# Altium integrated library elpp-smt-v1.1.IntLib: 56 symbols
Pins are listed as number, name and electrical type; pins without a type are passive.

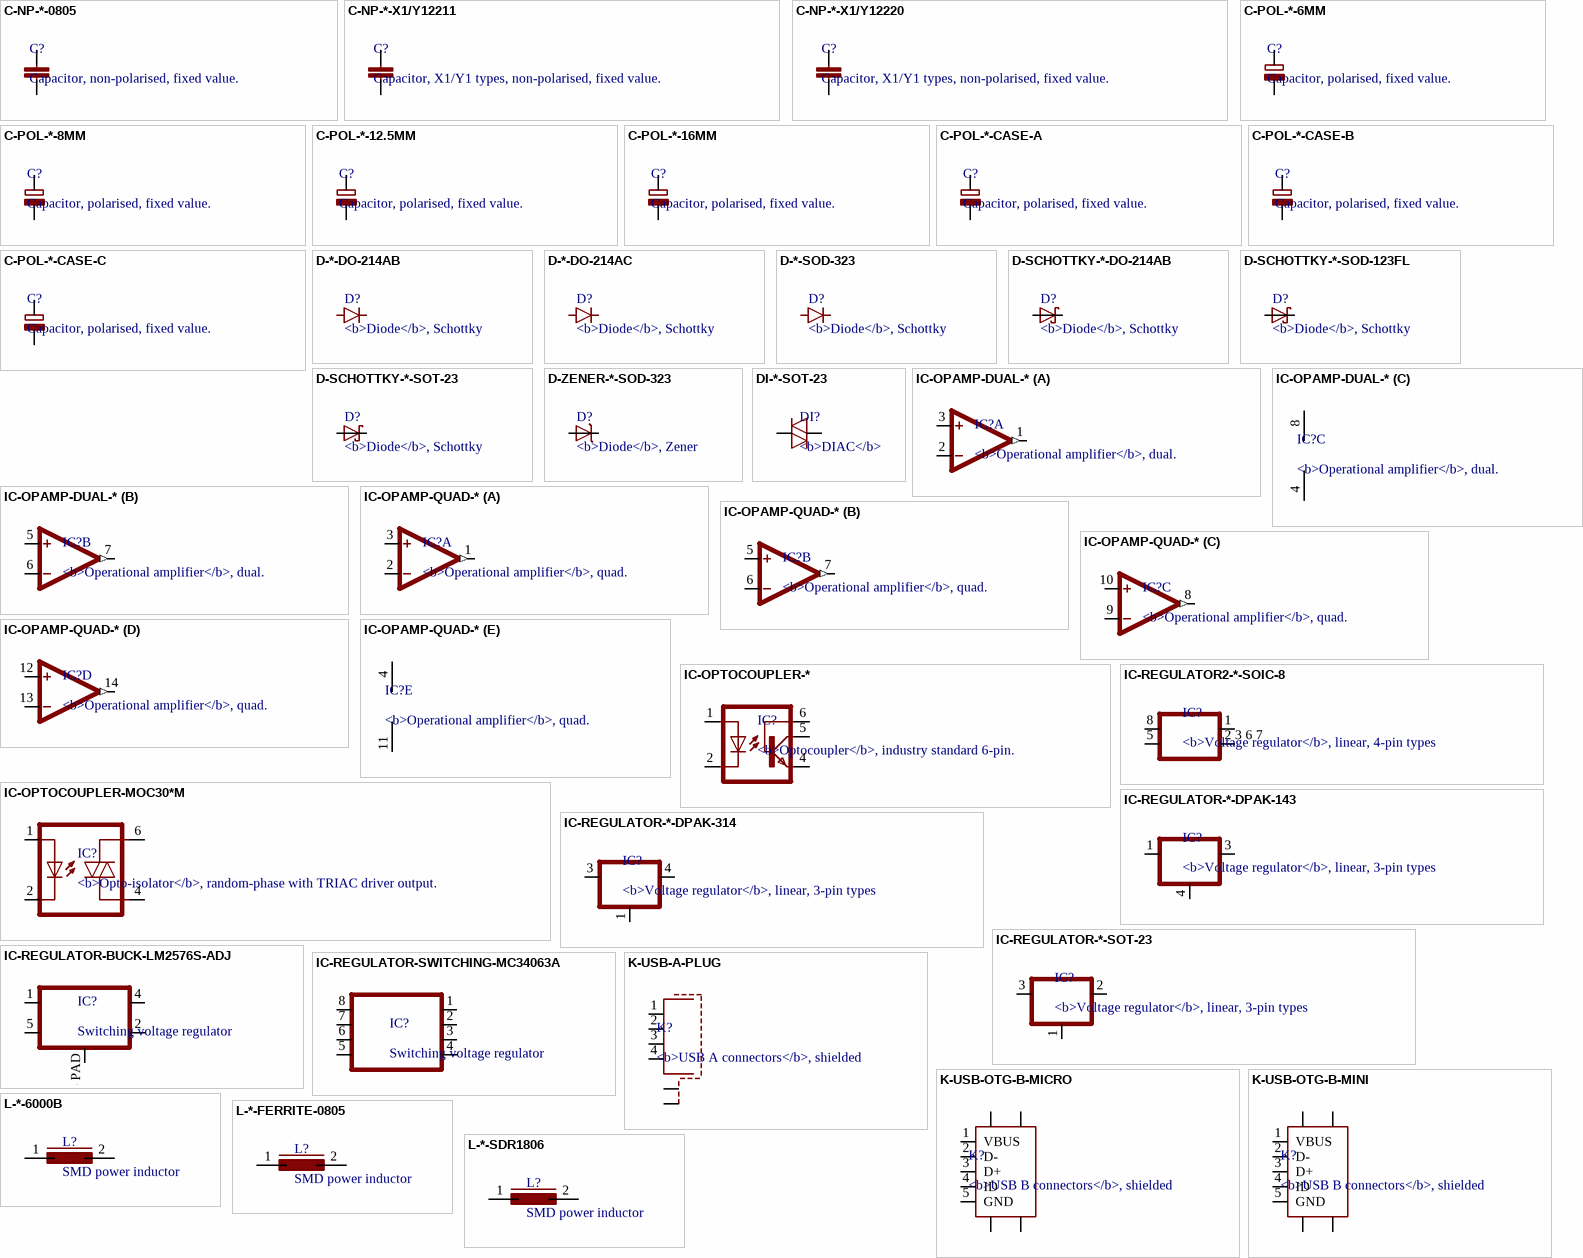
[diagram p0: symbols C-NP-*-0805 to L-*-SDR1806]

## C-NP-*-0805
designator C?, comment Capacitor, non-polarised, fixed value.
RS: 2644416; RS: 2644292; RS: 2644371; RS: 2644321; RS: 8029942; RS: 8029927; RS: 2644387; RS: 2644258; RS: 7236307; RS: 8029939; RS: 2644315; RS: 2644393; RS: 2644270
footprint ELPP-0805
pins: 1, 2

## C-NP-*-X1/Y12211
designator C?, comment Capacitor, X1/Y1 types, non-polarised, fixed value.
RS: 6197920; RS: 6197942
footprint ELPP-2211
pins: 1, 2

## C-NP-*-X1/Y12220
designator C?, comment Capacitor, X1/Y1 types, non-polarised, fixed value.
RS: 7234904; RS: 6530636; RS: 7739821
footprint ELPP-2220
pins: 1, 2

## C-POL-*-6MM
designator C?, comment Capacitor, polarised, fixed value.
RS: 7472821
footprint ELPP-CP-063-066
pins: +, -

## C-POL-*-8MM
designator C?, comment Capacitor, polarised, fixed value.
RS: 6284002
footprint ELPP-CP-080-083
pins: +, -

## C-POL-*-12.5MM
designator C?, comment Capacitor, polarised, fixed value.
RS: 7083869
footprint ELPP-CP-125-135
pins: +, -

## C-POL-*-16MM
designator C?, comment Capacitor, polarised, fixed value.
RS: 7083881; RS: 7083368
footprint ELPP-CP-160-170
pins: +, -

## C-POL-*-CASE-A
designator C?, comment Capacitor, polarised, fixed value.
RS: 538-2313; RS: 801-5441; RS: 648-0698; RS: 464-9104; RS: 538-2341
footprint ELPP-CP-CASE-A
pins: +, -

## C-POL-*-CASE-B
designator C?, comment Capacitor, polarised, fixed value.
RS: 801-5451
footprint ELPP-CP-CASE-B
pins: +, -

## C-POL-*-CASE-C
designator C?, comment Capacitor, polarised, fixed value.
RS: 801-5476; RS: 801-5460
footprint ELPP-CP-CASE-C
pins: +, -

## D-*-DO-214AB
designator D?, comment <b>Diode</b>, Schottky
RS: 8022219
footprint ELPP-DO-214AB
pins: A, C

## D-*-DO-214AC
designator D?, comment <b>Diode</b>, Schottky
RS: 7001230
footprint ELPP-DO-214AC
pins: A, C

## D-*-SOD-323
designator D?, comment <b>Diode</b>, Schottky
RS: 7613476
footprint ELPP-SOD-323
pins: A, C

## D-SCHOTTKY-*-DO-214AB
designator D?, comment <b>Diode</b>, Schottky
RS: 6880512
footprint ELPP-DO-214AB
pins: A, C

## D-SCHOTTKY-*-SOD-123FL
designator D?, comment <b>Diode</b>, Schottky
RS: 7925600
footprint ELPP-SOD-123FL
pins: A, C

## D-SCHOTTKY-*-SOT-23
designator D?, comment <b>Diode</b>, Schottky
RS: 7384829
footprint ELPP-SOT-23
pins: 1 A, 3 C

## D-ZENER-*-SOD-323
designator D?, comment <b>Diode</b>, Zener
RS: 508113; RS: 508103; RS: 508107; RS: 509207; RS: 509217
footprint ELPP-SOD-323
pins: A, C

## DI-*-SOT-23
designator DI?, comment <b>DIAC</b>
RS: 687-0965
footprint ELPP-SOT-23
pins: 1 2 1, 3 2

## IC-OPAMP-DUAL-*
designator IC?, comment <b>Operational amplifier</b>, dual.
RS: 7140827; RS: 5343481; RS: 7141142
footprint ELPP-SOIC-8
part A pins: 1 OUT (out), 2 -IN, 3 +IN
part B pins: 5 +IN, 6 -IN, 7 OUT (out)
part C pins: 4 V-, 8 V+

## IC-OPAMP-QUAD-*
designator IC?, comment <b>Operational amplifier</b>, quad.
RS: 5171876; RS: 5343532; RS: 8091489
footprint ELPP-SOIC-14
part A pins: 1 OUT (out), 2 -IN, 3 +IN
part B pins: 5 +IN, 6 -IN, 7 OUT (out)
part C pins: 8 OUT (out), 9 -IN, 10 +IN
part D pins: 12 +IN, 13 -IN, 14 OUT (out)
part E pins: 4 V+, 11 V-

## IC-OPTOCOUPLER-*
designator IC?, comment <b>Optocoupler</b>, industry standard 6-pin.
RS: 8051223; RS: 6712695
footprint ELPP-SMDIP-6
pins: 1 A, 2 C, 4 EMI, 5 COL, 6 BAS

## IC-OPTOCOUPLER-MOC30*M
designator IC?, comment <b>Opto-isolator</b>, random-phase with TRIAC driver output.
RS: 8065991
footprint ELPP-SMDIP-6
pins: 1 A, 2 C, 4 A1, 6 A2

## IC-REGULATOR2-*-SOIC-8
designator IC?, comment <b>Voltage regulator</b>, linear, 4-pin types
RS: 6869029; RS: 7958448
footprint ELPP-SOIC-8
pins: 1 VO, 2 3 6 7 COM, 5 ~{EN}, 8 VI

## IC-REGULATOR-*-DPAK-143
designator IC?, comment <b>Voltage regulator</b>, linear, 3-pin types
RS: 8065030
footprint ELPP-DPAK
pins: 1 VI, 3 VO, 4 COM

## IC-REGULATOR-*-DPAK-314
designator IC?, comment <b>Voltage regulator</b>, linear, 3-pin types
RS: 6869252
footprint ELPP-DPAK
pins: 1 COM, 3 VI, 4 VO

## IC-REGULATOR-*-SOT-23
designator IC?, comment <b>Voltage regulator</b>, linear, 3-pin types
RS: 6694850; RS: 6989044
footprint ELPP-SOT-23
pins: 1 COM, 2 VO, 3 VI

## IC-REGULATOR-BUCK-LM2576S-ADJ
designator IC?, comment Switching voltage regulator
RS: 5333232
footprint ELPP-TO-263-5
pins: 1 VI, 2 VO, 3 PAD COM, 4 FB, 5 EN

## IC-REGULATOR-SWITCHING-MC34063A
designator IC?, comment Switching voltage regulator
RS: 6618436
footprint ELPP-SOIC-8
pins: 1, 2, 3, 4, 5, 6, 7, 8

## K-USB-A-PLUG
designator K?, comment <b>USB A connectors</b>, shielded
RS: 7378795
footprint ELPP-USB-A-PLUG-SMT
pins: 1, 2, 3, 4, S1, S2

## K-USB-OTG-B-MICRO
designator K?, comment <b>USB B connectors</b>, shielded
RS: 7025475
footprint ELPP-USB-B-MICRO-BOTTOM
pins: 1 VBUS, 2 D-, 3 D+, 4 ID, 5 GND, S1, S2, S3, S4

## K-USB-OTG-B-MINI
designator K?, comment <b>USB B connectors</b>, shielded
RS: 6661099
footprint ELPP-USB-B-MINI
pins: 1 VBUS, 2 D-, 3 D+, 4 ID, 5 GND, S1, S2, S3, S4

## L-*-6000B
designator L?, comment SMD power inductor
RS: 7496414
footprint ELPP-L-6000B
pins: 1, 2

## L-*-FERRITE-0805
designator L?, comment SMD power inductor
footprint ELPP-0805
pins: 1, 2

## L-*-SDR1806
designator L?, comment SMD power inductor
RS: 7296548
footprint ELPP-L-SDR1806
pins: 1, 2

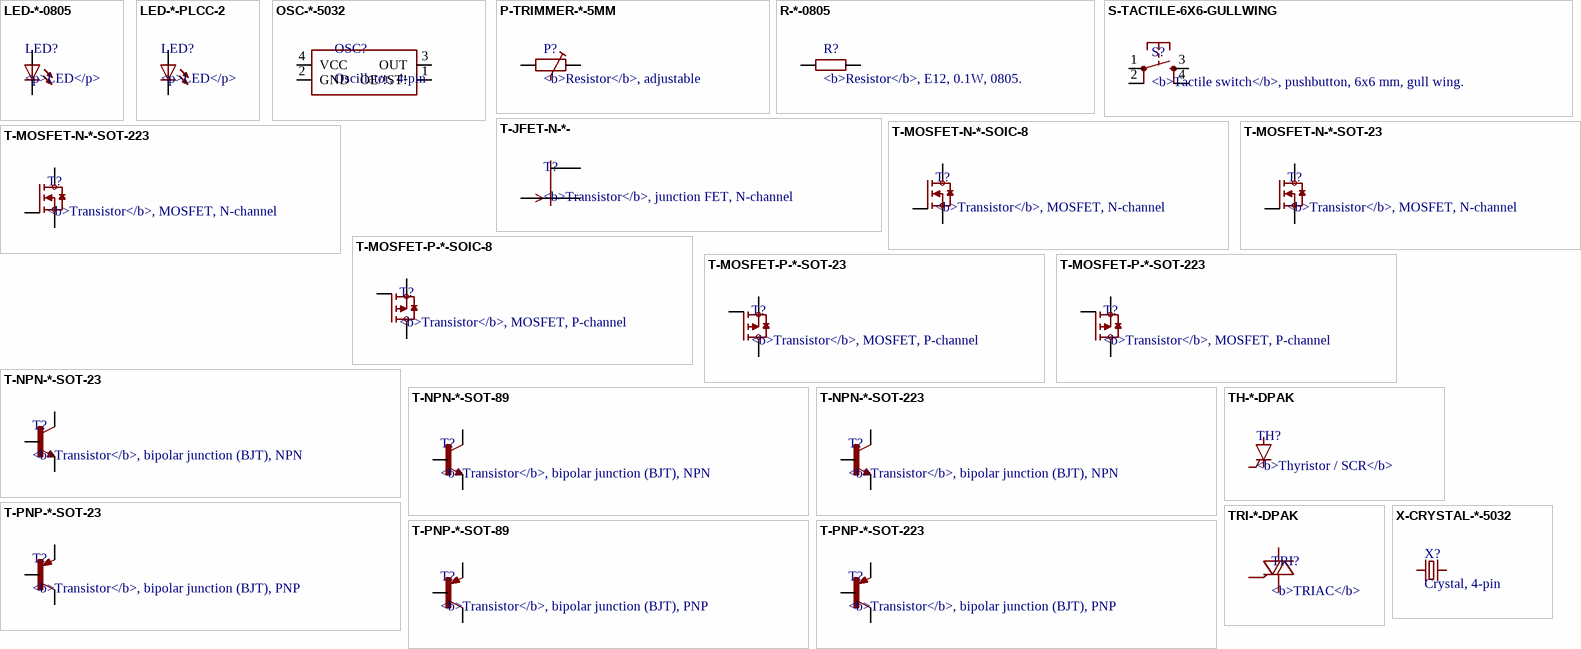
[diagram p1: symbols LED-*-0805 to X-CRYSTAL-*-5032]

## LED-*-0805
designator LED?, comment <p>LED</p>
RS: 8608879; RS: 8610037; RS: 4663813; RS: 8610046
footprint ELPP-LED-0805
pins: A, C

## LED-*-PLCC-2
designator LED?, comment <p>LED</p>
RS: 7734141
footprint ELPP-PLCC-2
pins: A, C

## OSC-*-5032
designator OSC?, comment Oscillator, 4-pin
RS: 7032183; RS: 7032199; RS: 7032206; RS: 7032177
footprint ELPP-5032A
pins: 1 OE/!ST!, 2 GND, 3 OUT, 4 VCC

## P-TRIMMER-*-5MM
designator P?, comment <b>Resistor</b>, adjustable
RS: 7870679; RS: 7870676; RS: 7870667; RS: 7870673; RS: 7870708; RS: 7870705
footprint ELPP-TRIMMER-SQUARE-5MM
pins: 1, 2, 3

## R-*-0805
designator R?, comment <b>Resistor</b>, E12, 0.1W, 0805.
RS: 2230146; RS: 2230691; RS: 2230297; RS: 2230562; RS: reel only; RS: 2230152; RS: 2230708; RS: 2230304; RS: 2230578; RS: 2230168; RS: 2230714; RS: 2230310; RS: 2230584; RS: 2230180; RS: 2230720; RS: 2230326; RS: 2230590; RS: 2230196; RS: 2230427; RS: 2230433; RS: 2230449; RS: 2230461; RS: 2230821; RS: 6791046; RS: 6791058; RS: 6791061; RS: 7215473; RS: 7215470; RS: 7215482; RS: 7215495; RS: 2230742; RS: 2230332; RS: 2230607; RS: 2230203; RS: 2230758; RS: 2230348; RS: 2230613; RS: 2230219; RS: 2230477; RS: 2230483; RS: 6791238; RS: 6791244; RS: 7215492; RS: 7215505; RS: 2230764; RS: 2230354; RS: 2230629; RS: 2230225; RS: 2230770; RS: 2230360; RS: 2230635; RS: 2230247; RS: 2230499; RS: 2230506; RS: 6791383; RS: 7215518; RS: 7215515; RS: 2230786; RS: 2230376; RS: 2230641; RS: 2230253; RS: 2230528; RS: 6791500; RS: 7215527; RS: 2230792; RS: 2230382; RS: 2230657; RS: 2230269; RS: 2230534; RS: 6791581; RS: 7215530; RS: 2230809; RS: 2230405; RS: 2230663; RS: 2230275; RS: 2230540; RS: 7215537; RS: 2230815; RS: 2230411; RS: 2230685; RS: 2230281; RS: 2230556; RS: 7215549
footprint ELPP-0805
pins: 1, 2

## S-TACTILE-6X6-GULLWING
designator S?, comment <b>Tactile switch</b>, pushbutton, 6x6 mm, gull wing.
RS: 7931633
footprint EPP-S-TACT-6X6-SMT
pins: 1, 2, 3, 4

## T-JFET-N-*-
designator T?, comment <b>Transistor</b>, junction FET, N-channel
RS: 6262327; RS: 6262333; RS: 6262349
footprint ELPP-SOT-23
pins: 1 S, 2 D, 3 G

## T-MOSFET-N-*-SOIC-8
designator T?, comment <b>Transistor</b>, MOSFET, N-channel
RS: 6391885
footprint ELPP-SOIC-8
pins: 1 2 3 S, 4 G, 5 6 7 8 D

## T-MOSFET-N-*-SOT-23
designator T?, comment <b>Transistor</b>, MOSFET, N-channel
RS: 6900127
footprint ELPP-SOT-23
pins: 1 G, 2 S, 3 D

## T-MOSFET-N-*-SOT-223
designator T?, comment <b>Transistor</b>, MOSFET, N-channel
RS: 7982785
footprint ELPP-SOT-223
pins: 1 G, 2 4 D, 3 S

## T-MOSFET-P-*-SOIC-8
designator T?, comment <b>Transistor</b>, MOSFET, P-channel
RS: 7259246
footprint ELPP-SOIC-8
pins: 1 2 3 S, 4 G, 5 6 7 8 D

## T-MOSFET-P-*-SOT-23
designator T?, comment <b>Transistor</b>, MOSFET, P-channel
RS: 6532288
footprint ELPP-SOT-23
pins: 1 G, 2 S, 3 D

## T-MOSFET-P-*-SOT-223
designator T?, comment <b>Transistor</b>, MOSFET, P-channel
RS: 7082469
footprint ELPP-SOT-223
pins: 1 G, 2 4 D, 3 S

## T-NPN-*-SOT-23
designator T?, comment <b>Transistor</b>, bipolar junction (BJT), NPN
RS: 4845065
footprint ELPP-SOT-23
pins: 1 B, 2 E, 3 C

## T-NPN-*-SOT-89
designator T?, comment <b>Transistor</b>, bipolar junction (BJT), NPN
RS: 4452130
footprint ELPP-SOT-89
pins: B, C, E

## T-NPN-*-SOT-223
designator T?, comment <b>Transistor</b>, bipolar junction (BJT), NPN
RS: 8015621
footprint ELPP-SOT-223
pins: 1 B, 2 4 C, 3 E

## T-PNP-*-SOT-23
designator T?, comment <b>Transistor</b>, bipolar junction (BJT), PNP
RS: 508236
footprint ELPP-SOT-23
pins: 1 B, 2 E, 3 C

## T-PNP-*-SOT-89
designator T?, comment <b>Transistor</b>, bipolar junction (BJT), PNP
RS: 4368013
footprint ELPP-SOT-89
pins: B, C, E

## T-PNP-*-SOT-223
designator T?, comment <b>Transistor</b>, bipolar junction (BJT), PNP
RS: 7114979
footprint ELPP-SOT-223
pins: 1 B, 2 4 C, 3 E

## TH-*-DPAK
designator TH?, comment <b>Thyristor / SCR</b>
RS: 8079940
footprint ELPP-DPAK
pins: 1 C, 3 G, 4 A

## TRI-*-DPAK
designator TRI?, comment <b>TRIAC</b>
RS: 7920709
footprint ELPP-DPAK
pins: 1 T1, 3 G, 4 T2

## X-CRYSTAL-*-5032
designator X?, comment Crystal, 4-pin
RS: 7031991; RS: 7032010; RS: 7032026; RS: 7031997
footprint ELPP-5032B
pins: 1, 2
